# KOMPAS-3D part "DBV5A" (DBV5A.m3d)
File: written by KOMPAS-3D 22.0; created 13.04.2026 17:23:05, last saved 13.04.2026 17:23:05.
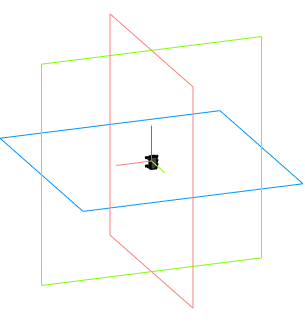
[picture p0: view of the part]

Document properties: Автор: Andrey; Полное имя файла: C:\Users\User1\Documents\DBV5A.m3d

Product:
- Part/product: DBV5A

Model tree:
1. Операция без истории:1
2. Операция без истории:2
3. Операция без истории:3
4. Операция без истории:4
5. Операция без истории:5
6. Операция без истории:6
7. Операция без истории:7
